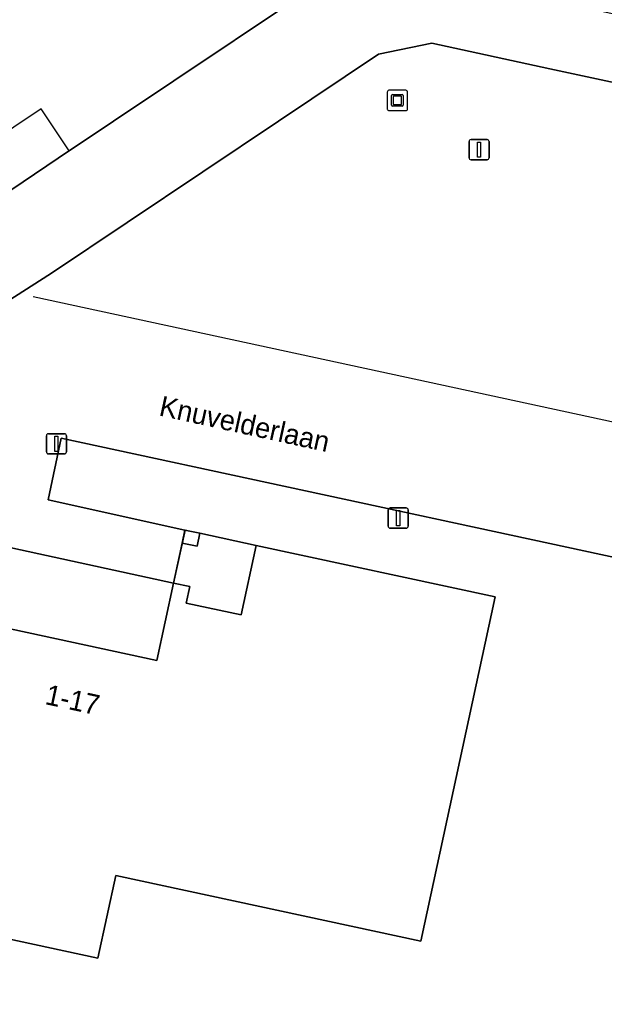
# Model space of a CAD drawing. Extents: x 161347 to 161881, y 382161 to 382804.
# Drawn here: x 161473.77 to 161502.68, y 382456.06 to 382505.01 of the extents above; entities that cross this region are included whole.
import ezdxf

# ---------------------------------------------------------------- set-up
doc = ezdxf.new("R2010")
doc.units = 0
for name, color, linetype in [('IMGEO_Erf', 7, 'Continuous'), ('IMGEO_Kunstobject', 7, 'Continuous'), ('IMGEO_Lichtmast', 7, 'Continuous'), ('IMGEO_Lijnafwatering', 7, 'Continuous'), ('IMGEO_Openbare_ruimte_label', 7, 'Continuous'), ('IMGEO_Pand', 7, 'Continuous'), ('IMGEO_Pand_nummerreeks', 7, 'Continuous'), ('IMGEO_Pand_overbouw', 7, 'Continuous'), ('IMGEO_Voetpad_open', 7, 'Continuous')]:
    doc.layers.add(name, color=color, linetype=linetype)

msp = doc.modelspace()

# ---------------------------------------------------------------- linework, layer by layer
at = {"layer": 'IMGEO_Erf'}
for points in [[(161490.393, 382508.028), (161478.402, 382500), (161475.671, 382498.172), (161472.197, 382495.844), (161457.968, 382486.306), (161464.119, 382485.318), (161475.341, 382492.496), (161486.569, 382500), (161491.524, 382503.311), (161494.163, 382503.857), (161500, 382502.6), (161512.072, 382500), (161520.272, 382498.234), (161522.532, 382496.667), (161539.309, 382469.447), (161545.974, 382467.342), (161536.968, 382481.919), (161534.501, 382485.913), (161525.798, 382500), (161525.522, 382500.446), (161522.985, 382502.254), (161514.037, 382504.398), (161513.736, 382503.008), (161502.162, 382505.515)], [(161529.133, 382472.859), (161500, 382479.131), (161475.815, 382484.338), (161475.174, 382481.282), (161481.945, 382479.796), (161482.684, 382479.645), (161485.462, 382479.04), (161497.294, 382476.49), (161493.615, 382459.469), (161478.517, 382462.719), (161477.639, 382458.64), (161456.073, 382463.283), (161459.231, 382477.951), (161480.549, 382473.354), (161481.379, 382477.176), (161445.186, 382485.044), (161443.651, 382484.283), (161457.359, 382456.669), (161460.674, 382449.996)]]:
    msp.add_lwpolyline(points, dxfattribs=at)
at = {"layer": 'IMGEO_Kunstobject'}
for p, q in [((161491.952, 382501.446), (161491.952, 382500.605)), ((161491.952, 382501.446), (161491.952, 382500.605)), ((161492.868, 382501.53), (161492.027, 382501.53)), ((161492.868, 382501.53), (161492.027, 382501.53)), ((161492.166, 382500.794), (161492.166, 382501.268)), ((161492.216, 382501.318), (161492.69, 382501.318)), ((161492.246, 382501.218), (161492.246, 382500.844)), ((161492.64, 382501.238), (161492.266, 382501.238)), ((161492.66, 382500.844), (161492.66, 382501.218)), ((161492.74, 382501.268), (161492.74, 382500.794)), ((161492.952, 382500.614), (161492.952, 382501.455)), ((161492.952, 382500.614), (161492.952, 382501.455)), ((161492.69, 382500.744), (161492.216, 382500.744)), ((161492.266, 382500.824), (161492.64, 382500.824)), ((161492.036, 382500.53), (161492.877, 382500.53)), ((161492.036, 382500.53), (161492.877, 382500.53))]:
    msp.add_line(p, q, dxfattribs=at)
for centre, radius, start, end in [((161492.03, 382501.452), 0.0779, 92.4484, 184.2845), ((161492.03, 382501.452), 0.0779, 92.4484, 184.2845), ((161492.216, 382501.268), 0.05, 90, 180), ((161492.266, 382501.218), 0.02, 90, 180), ((161492.64, 382501.218), 0.02, 360, 90), ((161492.69, 382501.268), 0.05, 360, 90), ((161492.874, 382501.452), 0.0779, 2.4484, 94.2845), ((161492.874, 382501.452), 0.0779, 2.4484, 94.2845), ((161492.03, 382500.608), 0.0779, 182.4484, 274.2845), ((161492.03, 382500.608), 0.0779, 182.4484, 274.2845), ((161492.216, 382500.794), 0.05, 180, 270), ((161492.266, 382500.844), 0.02, 180, 270), ((161492.64, 382500.844), 0.02, 270, 0), ((161492.69, 382500.794), 0.05, 270, 0), ((161492.874, 382500.608), 0.0779, 272.4484, 4.2845), ((161492.874, 382500.608), 0.0779, 272.4484, 4.2845)]:
    msp.add_arc(centre, radius, start, end, dxfattribs=at)
at = {"layer": 'IMGEO_Lichtmast'}
for p, q in [((161496.095, 382499.097), (161496.885, 382499.097)), ((161496.885, 382499.097), (161496.095, 382499.097)), ((161495.995, 382498.197), (161495.995, 382498.997)), ((161495.995, 382498.997), (161495.995, 382498.197)), ((161496.985, 382498.997), (161496.985, 382498.197)), ((161496.985, 382498.197), (161496.985, 382498.997)), ((161496.885, 382498.097), (161496.095, 382498.097)), ((161496.095, 382498.097), (161496.885, 382498.097)), ((161475.091, 382483.659), (161475.091, 382484.459)), ((161475.091, 382484.459), (161475.091, 382483.659)), ((161475.191, 382484.559), (161475.981, 382484.559)), ((161475.981, 382484.559), (161475.191, 382484.559)), ((161476.081, 382484.459), (161476.081, 382483.659)), ((161476.081, 382483.659), (161476.081, 382484.459)), ((161475.981, 382483.559), (161475.191, 382483.559)), ((161475.191, 382483.559), (161475.981, 382483.559)), ((161491.995, 382479.987), (161491.995, 382480.787)), ((161491.995, 382480.787), (161491.995, 382479.987)), ((161492.095, 382480.887), (161492.885, 382480.887)), ((161492.885, 382480.887), (161492.095, 382480.887)), ((161492.985, 382480.787), (161492.985, 382479.987)), ((161492.985, 382479.987), (161492.985, 382480.787)), ((161492.885, 382479.887), (161492.095, 382479.887)), ((161492.095, 382479.887), (161492.885, 382479.887))]:
    msp.add_line(p, q, dxfattribs=at)
for points in [[(161496.415, 382498.972), (161496.565, 382498.972), (161496.565, 382498.222), (161496.415, 382498.222), (161496.415, 382498.972)], [(161475.511, 382484.434), (161475.661, 382484.434), (161475.661, 382483.684), (161475.511, 382483.684), (161475.511, 382484.434)], [(161492.415, 382480.762), (161492.565, 382480.762), (161492.565, 382480.012), (161492.415, 382480.012), (161492.415, 382480.762)]]:
    msp.add_lwpolyline(points, dxfattribs=at)
for centre, start, end in [((161496.095, 382498.997), 90, 180), ((161496.095, 382498.997), 90, 180), ((161496.885, 382498.997), 0, 90), ((161496.885, 382498.997), 360, 90), ((161496.095, 382498.197), 180, 270), ((161496.095, 382498.197), 180, 270), ((161496.885, 382498.197), 270, 0), ((161496.885, 382498.197), 270, 0), ((161475.191, 382484.459), 90, 180), ((161475.191, 382484.459), 90, 180), ((161475.981, 382484.459), 0, 90), ((161475.981, 382484.459), 360, 90), ((161475.191, 382483.659), 180, 270), ((161475.191, 382483.659), 180, 270), ((161475.981, 382483.659), 270, 0), ((161475.981, 382483.659), 270, 0), ((161492.095, 382480.787), 90, 180), ((161492.095, 382480.787), 90, 180), ((161492.885, 382480.787), 0, 90), ((161492.885, 382480.787), 360, 90), ((161492.095, 382479.987), 180, 270), ((161492.095, 382479.987), 180, 270), ((161492.885, 382479.987), 270, 0), ((161492.885, 382479.987), 270, 0)]:
    msp.add_arc(centre, 0.1, start, end, dxfattribs=at)
at = {"layer": 'IMGEO_Lijnafwatering'}
for points in [[(161494.119, 382487.072), (161474.436, 382491.33)], [(161513.801, 382482.815), (161494.119, 382487.072)]]:
    msp.add_lwpolyline(points, dxfattribs=at)
at = {"layer": 'IMGEO_Pand'}
msp.add_lwpolyline([(161463.38, 382509.249), (161449.506, 382500), (161449.044, 382499.691), (161455.008, 382490.746), (161457.968, 382486.306), (161472.197, 382495.844), (161475.671, 382498.172), (161478.402, 382500), (161490.393, 382508.028)], dxfattribs=at)
for points in [[(161481.813, 382479.147), (161482.551, 382478.996), (161482.684, 382479.645), (161481.945, 382479.796)], [(161485.462, 382479.04), (161484.72, 382475.599), (161482.012, 382476.182), (161482.19, 382477.001), (161481.379, 382477.176), (161480.549, 382473.354), (161459.231, 382477.951), (161456.073, 382463.283), (161477.639, 382458.64), (161478.517, 382462.719), (161493.615, 382459.469), (161497.294, 382476.49)]]:
    msp.add_lwpolyline(points, close=True, dxfattribs=at)
at = {"layer": 'IMGEO_Pand_overbouw'}
for points in [[(161474.826, 382500.62), (161470.803, 382497.924), (161472.197, 382495.844), (161475.671, 382498.172), (161476.221, 382498.54)], [(161485.462, 382479.04), (161481.948, 382479.797), (161481.379, 382477.176), (161482.19, 382477.001), (161482.012, 382476.182), (161484.72, 382475.599)]]:
    msp.add_lwpolyline(points, close=True, dxfattribs=at)
at = {"layer": 'IMGEO_Voetpad_open'}
msp.add_lwpolyline([(161512.072, 382500), (161500, 382502.6), (161494.163, 382503.857), (161491.524, 382503.311), (161486.569, 382500), (161475.341, 382492.496), (161464.119, 382485.318), (161457.968, 382486.306), (161455.008, 382490.746), (161441.46, 382488.708), (161443.651, 382484.283), (161445.186, 382485.044), (161481.379, 382477.176), (161481.813, 382479.147), (161481.945, 382479.796), (161475.174, 382481.282), (161475.815, 382484.338), (161500, 382479.131), (161529.133, 382472.859)], dxfattribs=at)
msp.add_lwpolyline([(161482.684, 382479.645), (161482.551, 382478.996), (161481.813, 382479.147), (161481.379, 382477.176), (161482.19, 382477.001), (161482.012, 382476.182), (161484.72, 382475.599), (161485.462, 382479.04)], close=True, dxfattribs=at)

# ---------------------------------------------------------------- texts
at = {"layer": 'IMGEO_Openbare_ruimte_label'}
msp.add_text('Knuvelderlaan', height=1, rotation=347.7011, dxfattribs=at).set_placement((161480.614, 382485.466))
at = {"layer": 'IMGEO_Pand_nummerreeks'}
msp.add_text('1-17', height=1, rotation=347.8314, dxfattribs=at).set_placement((161474.976, 382471.2))

doc.saveas('drawing.dxf')
